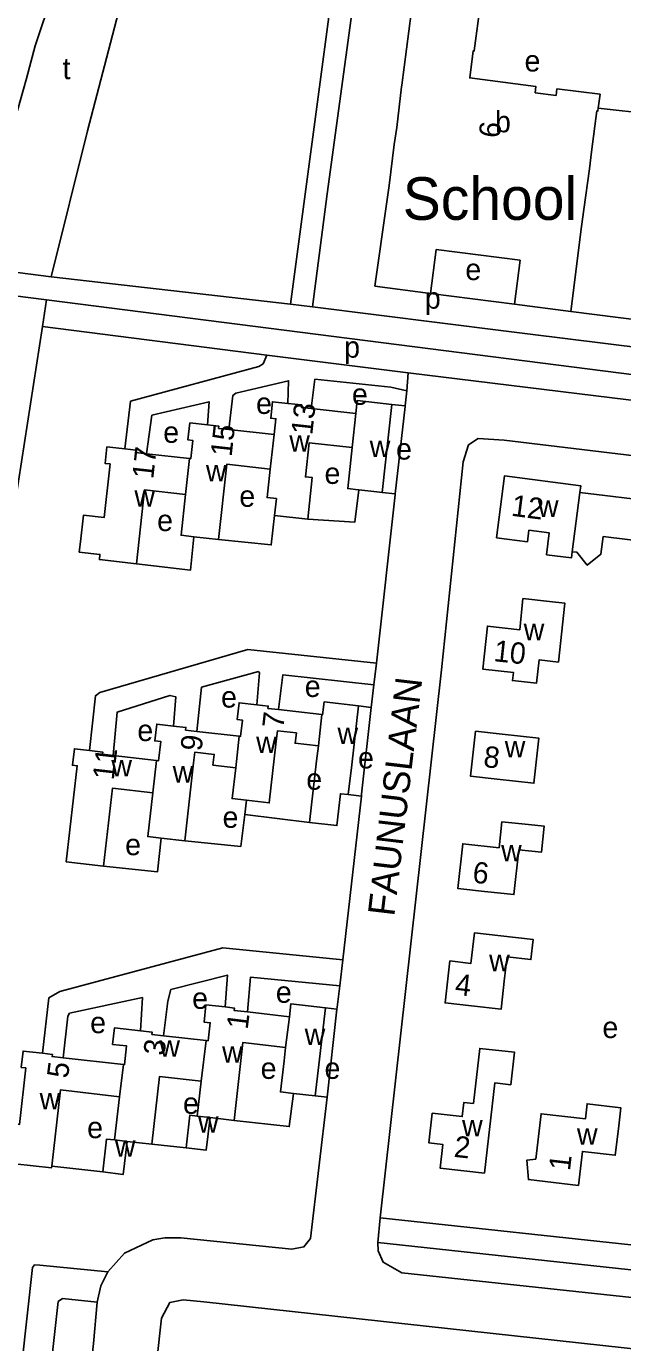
# Model space of a CAD drawing. Extents: x 161773 to 163836, y 384796 to 386521.
# Drawn here: x 162246.8 to 162358.6, y 385877.5 to 386124.5 of the extents above; entities that cross this region are included whole.
import ezdxf

# ---------------------------------------------------------------- set-up
doc = ezdxf.new("R2010")
doc.units = 0
for name, color, linetype in [('BLT_Basislijn', 7, 'Continuous'), ('BLT_Bebouwing', 7, 'Continuous'), ('BLT_Bebouwing_beschrifting', 7, 'Continuous'), ('BLT_Centroide', 7, 'Continuous'), ('BLT_Huisnummer', 7, 'Continuous'), ('BLT_Onderverdeling_panden', 7, 'Continuous'), ('BLT_Straatnaam', 7, 'Continuous')]:
    doc.layers.add(name, color=color, linetype=linetype)

msp = doc.modelspace()

# ---------------------------------------------------------------- linework, layer by layer
at = {"layer": 'BLT_Basislijn'}
for p, q in [((162304.99, 386137.39), (162296.29, 386072.34)), ((162366.48, 386107.73), (162354.02, 386109.11)), ((162251.43, 386077.47), (162258.26, 386104.86)), ((162237.78, 386079.23), (162251.43, 386077.47)), ((162296.29, 386072.34), (162251.43, 386077.47)), ((162236.88, 386074.82), (162250.57, 386073.14)), ((162250.57, 386073.14), (162249.79, 386068.11)), ((162250.57, 386073.14), (162405.56, 386053.32)), ((162322.54, 386074.33), (162338.28, 386072.29)), ((162300.43, 386071.84), (162296.29, 386072.34)), ((162336.26, 386067.3), (162300.43, 386071.84)), ((162249.79, 386068.11), (162241.92, 386017.31)), ((162291.87, 386062.74), (162249.79, 386068.11)), ((162336.26, 386067.3), (162340.72, 386066.73)), ((162318.39, 386059.45), (162291.87, 386062.74)), ((162318.09, 386056.07), (162318.39, 386059.45)), ((162318.09, 386056.07), (162317.79, 386053.24)), ((162315.29, 386053.51), (162317.79, 386053.24)), ((162313.47, 386037), (162315.96, 386036.72)), ((162312.41, 386004.95), (162311.94, 386000.88)), ((162311.94, 386000.88), (162311.45, 385996.65)), ((162309.04, 385996.94), (162311.45, 385996.65)), ((162288.08, 385979.22), (162287.74, 385976.55)), ((162309.59, 385980.03), (162306.1, 385949.29)), ((162307.14, 385980.29), (162309.59, 385980.03)), ((162287.74, 385976.55), (162299.89, 385975.07)), ((162306.1, 385949.29), (162305.53, 385944.43)), ((162302.84, 385940.29), (162305.01, 385940.06)), ((162303.16, 385923.5), (162305.01, 385940.06)), ((162300.96, 385923.74), (162303.16, 385923.5)), ((162276.72, 385914.01), (162270.32, 385914.7)), ((162261.13, 385909.48), (162251.54, 385910.59)), ((162312.67, 385896.24), (162313.11, 385900.9)), ((162313.11, 385900.9), (162487.53, 385882.12)), ((162312.67, 385896.24), (162486.1, 385877.57))]:
    msp.add_line(p, q, dxfattribs=at)
for points in [[(162254.86, 386140.04), (162248.46, 386120.76), (162246.78, 386114.69), (162245.11, 386108.63)], [(162267.07, 386138.67), (162261.82, 386118.49), (162258.26, 386104.86)], [(162300.43, 386071.84), (162303.21, 386093.04), (162308.45, 386131.55), (162315.12, 386130.72)], [(162368.44, 386124.01), (162377.83, 386122.84), (162378.37, 386122.52), (162370.77, 386063.4), (162369.98, 386063.13), (162340.72, 386066.73)], [(162366.48, 386107.73), (162371.43, 386107.21), (162366.61, 386068.7), (162348.88, 386070.92)], [(162291.87, 386062.74), (162291.16, 386061.11), (162290.36, 386060.61), (162266.33, 386054.11), (162265.27, 386045.16)], [(162295.83, 386053.7), (162295.94, 386057.94), (162286.04, 386055.6), (162285.52, 386055.2), (162284.76, 386048.79)], [(162300.19, 386052.75), (162300.9, 386058.23), (162315.1, 386056.72), (162318.09, 386056.07)], [(162318.39, 386059.45), (162391.31, 386050.49), (162404.97, 386048.73)], [(162280.74, 386049.65), (162281.03, 386054.01), (162270.31, 386051.48), (162269.34, 386044.25)], [(162315.96, 386036.72), (162317.78, 386053.09), (162317.79, 386053.24)], [(162313.11, 385900.9), (162324.65, 386003.69), (162328.7, 386042.76), (162329.67, 386045.91), (162331.52, 386047.14), (162336.37, 386046.82), (162391.99, 386040.11), (162393.98, 386038.7), (162394.67, 386037.26), (162394.3, 386031.81), (162386.9, 385961.46), (162492, 385948), (162502.84, 385946.15), (162504.84, 385944.19), (162504.96, 385941.44), (162504.67, 385940.04), (162487.53, 385882.12)], [(162309.11, 386037.48), (162308.36, 386031.41), (162299.53, 386031.99)], [(162315.96, 386036.72), (162315.94, 386036.52), (162312.41, 386004.95)], [(162293.31, 386032.68), (162292.7, 386027.13), (162282.8, 386028.19)], [(162278.21, 386028.69), (162277.55, 386022.39), (162267.41, 386023.62)], [(162258.64, 385988.57), (162259.72, 385998.83), (162260.53, 385999.43), (162288.29, 386007.54), (162312.41, 386004.95)], [(162278.76, 385992.15), (162279.63, 386000.45), (162290.28, 386003.37), (162290.52, 386003.16), (162290.01, 385997.16)], [(162311.94, 386000.88), (162294.86, 386002.76), (162294.03, 385996.24)], [(162263.03, 385987.64), (162263.83, 385995.78), (162273.69, 385998.91), (162274.79, 385998.64), (162274.4, 385993.16)], [(162311.45, 385996.65), (162309.63, 385980.38), (162309.59, 385980.03)], [(162287.74, 385976.55), (162286.98, 385970.57), (162276.49, 385971.63)], [(162261.26, 385966.87), (162271.38, 385965.81), (162272.05, 385972.14)], [(162249.82, 385931.75), (162251.02, 385942.17), (162253.05, 385943.32), (162283.64, 385951.56), (162306.1, 385949.29)], [(162272.5, 385935.05), (162273.3, 385941.54), (162273.9, 385943.75), (162284.47, 385946.44), (162284.04, 385940.44)], [(162288.25, 385939.51), (162288.8, 385946.02), (162305.53, 385944.43)], [(162305.01, 385940.06), (162305.05, 385940.43), (162305.53, 385944.43)], [(162253.7, 385930.92), (162254.58, 385938.7), (162254.9, 385939.28), (162268.54, 385942.21), (162268.21, 385935.99)], [(162262.04, 385890.76), (162265.21, 385894.27), (162270.49, 385896.76), (162272.77, 385897.12), (162275.74, 385897.1), (162296.57, 385895.02), (162298.83, 385895.41), (162300.07, 385897.01), (162303.16, 385923.5)], [(162296.88, 385924.21), (162296.07, 385918.01), (162285.75, 385919.17)], [(162312.67, 385896.24), (162312.77, 385894.67), (162313.69, 385892.54), (162317.19, 385890.56), (162477.99, 385873.28), (162483.44, 385873.42), (162485.48, 385875.36), (162486.1, 385877.57)], [(162262.04, 385890.76), (162249.29, 385892.02), (162248.28, 385892.03), (162247.96, 385891.53), (162231.14, 385739.66)], [(162260.03, 385885.07), (162260.77, 385888.14), (162262.04, 385890.76)], [(162260.03, 385885.07), (162253.54, 385885.74), (162252.74, 385885.17), (162236.52, 385739.12)], [(162260.03, 385885.07), (162259.38, 385877.3), (162244.41, 385741.03), (162243.6, 385739.8), (162242.55, 385739), (162241.05, 385738.73), (162236.52, 385739.12)], [(162421.09, 385869.66), (162280.08, 385885.14), (162276.18, 385885.47), (162273.68, 385884.97), (162272.15, 385882.05), (162261.23, 385783.38), (162256.71, 385739.19), (162258.62, 385737.22), (162315.92, 385731.49), (162319.96, 385731.49), (162321.33, 385732.35), (162321.81, 385732.99), (162322.55, 385735.84), (162329.57, 385810.51), (162330.36, 385810.78), (162333.99, 385810.59), (162407.18, 385803.55)]]:
    msp.add_lwpolyline(points, dxfattribs=at)
at = {"layer": 'BLT_Bebouwing'}
for p, q in [((162346.1, 386111.47), (162346.27, 386112.75)), ((162346.27, 386112.75), (162354.36, 386111.72)), ((162342.17, 386111.98), (162346.1, 386111.47)), ((162354.36, 386111.72), (162354.02, 386109.11)), ((162312.15, 386075.68), (162314.39, 386091.52)), ((162350.9, 386086.86), (162348.88, 386070.92)), ((162323.6, 386082.57), (162322.54, 386074.33)), ((162339.35, 386080.55), (162323.6, 386082.57)), ((162338.28, 386072.29), (162339.35, 386080.55)), ((162322.54, 386074.33), (162312.15, 386075.68)), ((162348.88, 386070.92), (162338.28, 386072.29)), ((162313.47, 386037), (162315.29, 386053.51)), ((162308.55, 386051.83), (162300.19, 386052.75)), ((162293.24, 386047.86), (162284.76, 386048.79)), ((162277.37, 386043.37), (162269.34, 386044.25)), ((162299.53, 386031.99), (162293.31, 386032.68)), ((162282.8, 386028.19), (162278.21, 386028.69)), ((162294.03, 385996.24), (162302.2, 385995.31)), ((162309.04, 385996.94), (162307.78, 385985.9)), ((162278.76, 385992.15), (162286.7, 385991.24)), ((162301.21, 385986.65), (162301.53, 385989.43)), ((162263.03, 385987.64), (162271.18, 385986.71)), ((162299.89, 385975.07), (162301.21, 385986.65)), ((162307.78, 385985.9), (162307.14, 385980.29)), ((162276.49, 385971.63), (162272.05, 385972.14)), ((162288.25, 385939.51), (162296.09, 385938.62)), ((162302.84, 385940.29), (162301.63, 385929.6)), ((162272.5, 385935.05), (162280.5, 385934.15)), ((162253.7, 385930.92), (162265, 385929.63)), ((162301.63, 385929.6), (162300.96, 385923.74)), ((162278.83, 385919.96), (162279.57, 385926.53)), ((162263.34, 385915.5), (162264.26, 385923.61)), ((162300.96, 385923.74), (162296.88, 385924.21)), ((162285.75, 385919.17), (162281.22, 385919.68)), ((162270.32, 385914.7), (162265.66, 385915.22))]:
    msp.add_line(p, q, dxfattribs=at)
for points in [[(162317.14, 386113.1), (162317.18, 386113.41), (162319.36, 386130.34)], [(162331.91, 386128.71), (162330.77, 386119.84), (162330.58, 386119.86), (162329.92, 386114.76), (162342.33, 386113.16), (162342.17, 386111.98)], [(162315.76, 386102.3), (162316.22, 386105.49), (162317.14, 386113.1)], [(162353.73, 386108.62), (162352.75, 386100.89), (162352.34, 386097.74)], [(162354.02, 386109.11), (162353.95, 386108.59), (162353.73, 386108.62)], [(162314.39, 386091.52), (162314.79, 386094.61), (162315.76, 386102.3)], [(162352.34, 386097.74), (162351.31, 386090.05), (162350.9, 386086.86)], [(162295.83, 386053.7), (162292.93, 386054.02), (162292.59, 386050.92), (162293.56, 386050.81), (162293.24, 386047.86)], [(162300.19, 386052.75), (162298.37, 386052.95), (162298.42, 386053.42), (162295.83, 386053.7)], [(162315.29, 386053.51), (162308.82, 386054.22), (162308.55, 386051.83)], [(162280.74, 386049.65), (162277.44, 386050.02), (162277.09, 386046.85), (162277.99, 386046.75), (162277.61, 386043.34), (162277.37, 386043.37)], [(162284.76, 386048.79), (162282.84, 386049.01), (162282.88, 386049.42), (162280.74, 386049.65)], [(162265.27, 386045.16), (162261.88, 386045.53), (162261.54, 386042.44), (162262.47, 386042.33), (162261.36, 386032.28), (162257.48, 386032.71), (162256.93, 386027.74), (162256.71, 386025.79), (162260.59, 386025.37), (162260.48, 386024.39), (162267.41, 386023.62)], [(162307.88, 386045.42), (162299.82, 386046.31), (162299.11, 386039.91), (162300.39, 386039.77), (162299.53, 386031.99)], [(162269.34, 386044.25), (162267.31, 386044.48), (162267.36, 386044.93), (162265.27, 386045.16)], [(162307.88, 386045.42), (162307.03, 386037.71), (162308.97, 386037.5), (162309.11, 386037.48)], [(162292.52, 386041.38), (162284.35, 386042.28), (162282.8, 386028.19)], [(162293.31, 386032.68), (162293.66, 386035.84), (162291.93, 386036.03), (162292.52, 386041.38)], [(162350.56, 386036.98), (162350.73, 386038.23), (162336.42, 386040.08), (162334.92, 386028.48)], [(162276.62, 386036.6), (162268.93, 386037.45), (162267.41, 386023.62)], [(162278.21, 386028.69), (162275.78, 386028.96), (162276.62, 386036.6)], [(162309.11, 386037.48), (162312.52, 386037.11), (162313.47, 386037)], [(162350.56, 386036.98), (162365.09, 386035.2), (162365.24, 386036.42), (162368.92, 386035.96), (162368.31, 386031)], [(162368.31, 386031), (162367.46, 386024.09), (162364.47, 386024.45), (162363.7, 386024.55), (162364.07, 386027.59), (162354.93, 386028.71), (162354.52, 386025.4), (162351.94, 386023.33), (162350, 386025.76), (162349.13, 386025.87)], [(162334.92, 386028.48), (162340.74, 386027.73), (162341.01, 386029.88), (162344.83, 386029.38), (162344.31, 386025.31), (162348.98, 386024.71), (162349.13, 386025.87)], [(162346.53, 386005.16), (162347.72, 386016.22), (162344.88, 386016.53), (162339.9, 386017.06), (162339.28, 386011.24), (162333.22, 386011.9), (162332.35, 386003.84), (162338.1, 386003.23), (162337.93, 386001.7), (162342.46, 386001.21), (162342.92, 386005.55), (162346.53, 386005.16)], [(162286.7, 385991.24), (162286.95, 385991.21), (162287.29, 385994.27), (162286.31, 385994.38), (162286.67, 385997.54), (162290.01, 385997.16)], [(162290.01, 385997.16), (162292.13, 385996.91), (162292.08, 385996.46), (162294.03, 385996.24)], [(162302.2, 385995.31), (162302.33, 385995.29), (162302.6, 385997.68), (162309.04, 385996.94)], [(162271.18, 385986.71), (162271.59, 385986.66), (162272, 385990.23), (162270.87, 385990.36), (162271.23, 385993.52), (162274.4, 385993.16)], [(162274.4, 385993.16), (162276.7, 385992.9), (162276.64, 385992.39), (162278.76, 385992.15)], [(162301.53, 385989.43), (162297.18, 385989.92), (162297.41, 385991.88), (162293.88, 385992.28), (162293.63, 385990.33), (162292.31, 385978.73), (162288.08, 385979.22)], [(162335.98, 385991.62), (162342.88, 385990.86), (162341.94, 385982.41), (162335.04, 385983.18), (162330.07, 385983.73), (162331.01, 385992.18), (162335.98, 385991.62)], [(162261.26, 385966.87), (162254.27, 385967.67), (162256.32, 385985.7), (162255.43, 385985.8), (162255.78, 385988.89), (162258.64, 385988.57)], [(162258.64, 385988.57), (162261.12, 385988.28), (162261.07, 385987.86), (162263.03, 385987.64)], [(162286.03, 385985.34), (162281.77, 385985.83), (162282, 385987.84), (162278.38, 385988.26), (162278.15, 385986.24), (162276.49, 385971.63)], [(162288.08, 385979.22), (162285.37, 385979.53), (162286.03, 385985.34)], [(162270.49, 385980.61), (162262.93, 385981.48), (162261.26, 385966.87)], [(162272.05, 385972.14), (162269.55, 385972.42), (162270.49, 385980.61)], [(162307.14, 385980.29), (162305.68, 385980.46), (162305, 385974.49), (162299.89, 385975.07)], [(162340.92, 385974.67), (162343.89, 385974.35), (162343.36, 385969.46), (162339.1, 385969.92), (162338.19, 385961.52), (162332.66, 385962.12), (162327.69, 385962.66), (162328.6, 385971.07), (162335.42, 385970.33), (162335.95, 385975.21), (162340.92, 385974.67)], [(162336.45, 385945.84), (162336.91, 385949.84), (162341.39, 385949.33), (162341.81, 385953.09), (162335.76, 385953.78), (162330.79, 385954.34), (162330.14, 385948.62), (162326.19, 385949.07), (162325.3, 385941.21), (162330.27, 385940.64), (162335.79, 385940.02), (162336.45, 385945.84)], [(162280.5, 385934.15), (162280.86, 385934.11), (162281.25, 385937.49), (162280.1, 385937.62), (162280.46, 385940.85), (162284.04, 385940.44)], [(162284.04, 385940.44), (162285.78, 385940.24), (162285.73, 385939.8), (162288.25, 385939.51)], [(162296.09, 385938.62), (162296.36, 385941.02), (162302.84, 385940.29)], [(162265, 385929.63), (162265.17, 385929.61), (162265.57, 385933.13), (162262.95, 385933.43), (162263.31, 385936.54), (162268.21, 385935.99)], [(162268.21, 385935.99), (162270.37, 385935.74), (162270.32, 385935.3), (162272.5, 385935.05)], [(162251.54, 385910.59), (162251.5, 385910.26), (162244.63, 385911.04), (162245, 385914.34), (162243.55, 385914.51), (162244.01, 385918.53), (162245.47, 385918.36), (162246.68, 385929.01), (162245.83, 385929.1), (162246.18, 385932.17), (162249.82, 385931.75)], [(162295.38, 385932.87), (162287.4, 385933.78), (162285.75, 385919.17)], [(162295.1, 385930.34), (162295.38, 385932.87)], [(162332.7, 385909.26), (162334.6, 385926.2), (162337.6, 385925.86), (162338.28, 385931.99), (162331.8, 385932.68), (162330.59, 385922.35), (162328.81, 385922.54), (162328.51, 385919.88), (162322.89, 385920.51), (162322.26, 385914.92), (162324.88, 385914.63), (162324.38, 385910.19), (162332.7, 385909.26)], [(162249.82, 385931.75), (162251.66, 385931.54), (162251.62, 385931.15), (162253.7, 385930.92)], [(162296.88, 385924.21), (162294.43, 385924.49), (162295.1, 385930.34)], [(162279.57, 385926.53), (162271.77, 385927.41), (162270.32, 385914.7)], [(162264.26, 385923.61), (162253.16, 385924.87), (162251.54, 385910.59)], [(162350.29, 385906.94), (162351.04, 385913.35), (162357.2, 385912.62), (162357.78, 385917.59), (162358.24, 385921.53), (162351.93, 385922.27), (162351.6, 385919.43), (162343.29, 385920.4), (162342.3, 385911.91), (162340.62, 385911.71), (162340.91, 385908.05), (162350.29, 385906.94)], [(162276.72, 385914.01), (162277.41, 385920.12), (162278.83, 385919.96)], [(162281.22, 385919.68), (162280.52, 385913.58), (162276.72, 385914.01)], [(162261.13, 385909.48), (162261.84, 385915.67), (162263.34, 385915.5)], [(162265.66, 385915.22), (162264.95, 385909.04), (162261.13, 385909.48)]]:
    msp.add_lwpolyline(points, dxfattribs=at)
at = {"layer": 'BLT_Onderverdeling_panden'}
for p, q in [((162307.88, 386045.42), (162308.55, 386051.83)), ((162292.52, 386041.38), (162293.24, 386047.86)), ((162276.62, 386036.6), (162277.37, 386043.37)), ((162349.13, 386025.87), (162350.56, 386036.98)), ((162301.53, 385989.43), (162302.2, 385995.31)), ((162286.03, 385985.34), (162286.7, 385991.24)), ((162270.49, 385980.61), (162271.18, 385986.71)), ((162296.09, 385938.62), (162295.38, 385932.87)), ((162280.5, 385934.15), (162279.57, 385926.53)), ((162265, 385929.63), (162264.26, 385923.61)), ((162278.83, 385919.96), (162281.22, 385919.68)), ((162263.34, 385915.5), (162265.66, 385915.22))]:
    msp.add_line(p, q, dxfattribs=at)

# ---------------------------------------------------------------- texts
at = {"layer": 'BLT_Bebouwing_beschrifting'}
msp.add_text('School', height=8, dxfattribs=at).set_placement((162317.35, 386088.14))
at = {"layer": 'BLT_Centroide'}
for s, p in [('t', (162253.57, 386114.54)), ('e', (162340.19, 386115.97)), ('b', (162334.66, 386104.56)), ('e', (162329.09, 386076.84)), ('p', (162321.5, 386071.47)), ('p', (162306.37, 386062.27)), ('e', (162307.83, 386053.43)), ('e', (162289.85, 386051.72)), ('e', (162272.45, 386046.3)), ('w', (162296.08, 386044.66)), ('w', (162311.16, 386043.61)), ('e', (162316.1, 386043.15)), ('w', (162280.45, 386039.09)), ('e', (162302.69, 386038.59)), ('w', (162267.05, 386034.31)), ('e', (162286.71, 386034.3)), ('w', (162342.7, 386032.41)), ('e', (162271.3, 386029.74)), ('w', (162340.03, 386009.27)), ('e', (162298.98, 385998.61)), ('e', (162283.29, 385996.62)), ('e', (162267.59, 385990.34)), ('w', (162289.86, 385988.12)), ('w', (162305.12, 385989.78)), ('w', (162336.48, 385987.28)), ('w', (162262.72, 385983.69)), ('e', (162308.97, 385985.2)), ('w', (162274.22, 385982.56)), ('e', (162299.27, 385981.2)), ('e', (162283.57, 385974.06)), ('e', (162265.31, 385968.92)), ('w', (162335.8, 385967.77)), ('w', (162333.55, 385947.16)), ('e', (162293.56, 385941.23)), ('e', (162277.87, 385940.09)), ('e', (162258.75, 385935.52)), ('e', (162354.79, 385934.61)), ('w', (162298.97, 385933.31)), ('w', (162271.72, 385931.09)), ('w', (162283.48, 385930)), ('e', (162290.71, 385926.95)), ('e', (162302.69, 385926.95)), ('w', (162249.27, 385921.22)), ('e', (162276.15, 385920.39)), ('w', (162278.97, 385916.84)), ('e', (162258.18, 385915.82)), ('w', (162328.48, 385916.14)), ('w', (162350.02, 385914.59)), ('w', (162263.39, 385912.36))]:
    msp.add_text(s, height=4, dxfattribs=at).set_placement(p)
at = {"layer": 'BLT_Huisnummer'}
for s, rotation, p in [('6', 82.7848, (162335.52, 386103.34)), ('13', 83.7057, (162300.38, 386047.67)), ('15', 83.7054, (162285.26, 386043.59)), ('17', 83.7081, (162270.57, 386039.39)), ('12', 352.647, (162337.56, 386032.63)), ('10', 353.8634, (162334.29, 386005.34)), ('7', 83.4876, (162294.96, 385992.59)), ('9', 83.4925, (162279.62, 385988.33)), ('8', 353.651, (162332.36, 385985.5)), ('11', 83.4866, (162263.17, 385982.92)), ('6', 353.8117, (162330.31, 385963.79)), ('4', 353.5244, (162327.02, 385942.77)), ('1', 82.9781, (162288.27, 385936.11)), ('3', 82.9574, (162272.66, 385931.2)), ('5', 82.9622, (162254.58, 385926.94)), ('2', 353.6235, (162326.83, 385912.33)), ('1', 83.3083, (162348.7, 385909.59))]:
    msp.add_text(s, height=4, rotation=rotation, dxfattribs=at).set_placement(p)
at = {"layer": 'BLT_Straatnaam'}
msp.add_text('FAUNUSLAAN', height=5, rotation=83.2692, dxfattribs=at).set_placement((162315.76, 385957.33))

doc.saveas('drawing.dxf')
